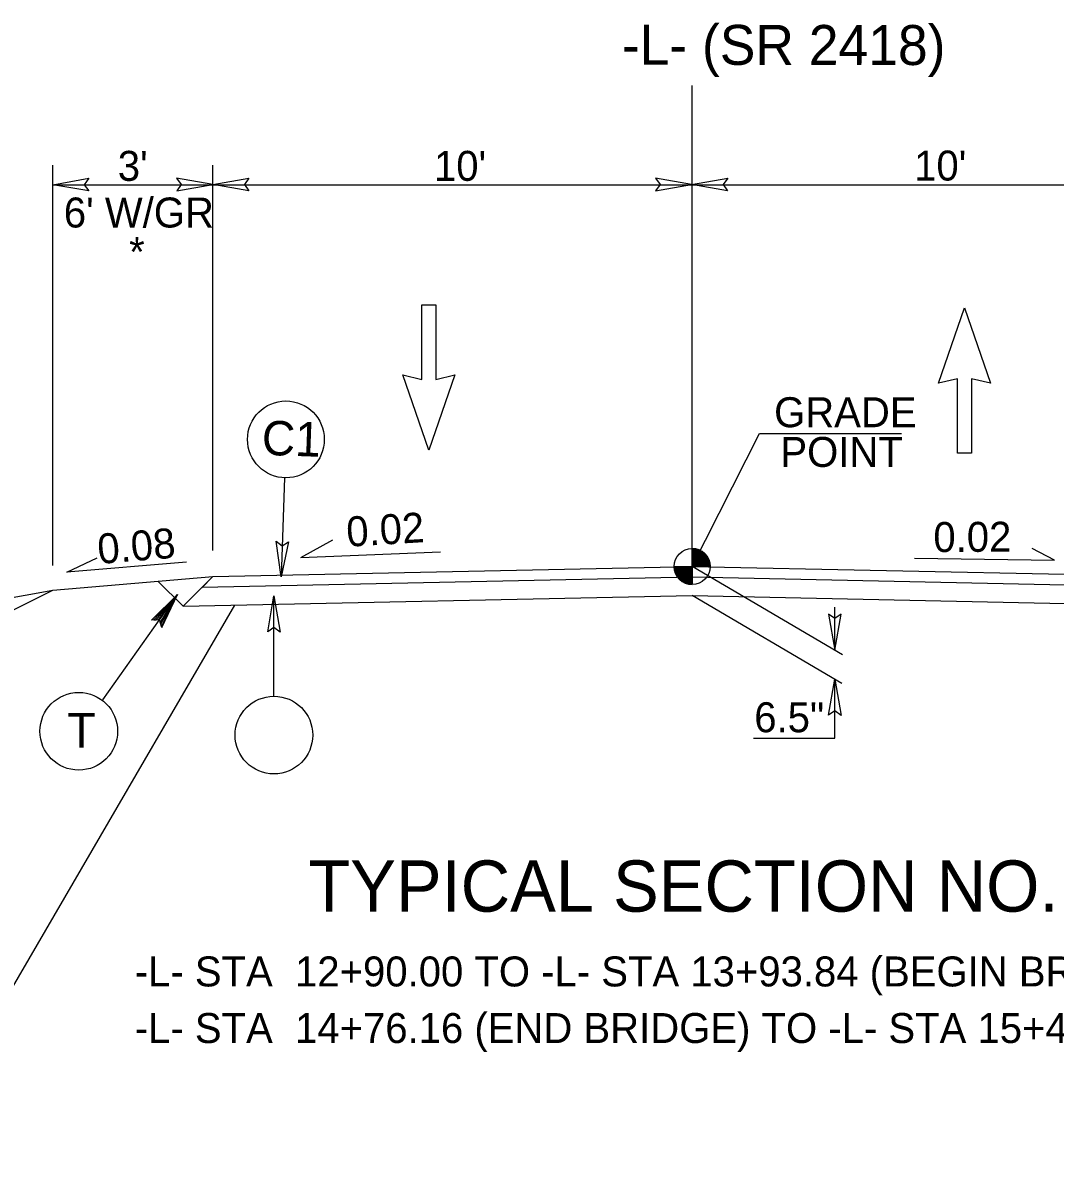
# Model space of a CAD drawing. Extents: x 1542177 to 1542464, y 45134 to 45344.
# Drawn here: x 1542264.12 to 1542284.79, y 45256.85 to 45279.65 of the extents above; entities that cross this region are included whole.
import ezdxf

# ---------------------------------------------------------------- set-up
doc = ezdxf.new("R2010")
doc.units = 0
for name, color, linetype in [('Default', 7, 'Continuous'), ('Old_Level_2', 7, 'Continuous'), ('Typical Detail Wedge3 CELL', 7, 'Continuous'), ('Typical ID Circle CELL', 7, 'Continuous'), ('Typical Terminator CELL', 7, 'Continuous'), ('Typical Text ID Circle CELL', 7, 'Continuous')]:
    doc.layers.add(name, color=color, linetype=linetype)

# ---------------------------------------------------------------- blocks, each defined once
blk = doc.blocks.new('GP')
at = {"layer": 'Default'}
blk.add_line((-0.001, -0.343), (0, 0), dxfattribs=at)
for points in [[(0.343, 0), (0.343, 0), (0, 0), (0, 0.343), (0, 0.343)], [(0.003, 0.343), (0.003, 0.343), (0.003, 0)], [(0.01, 0.343), (0.01, 0)], [(0.017, 0.342), (0.017, 0)], [(0.024, 0.342), (0.024, 0)], [(0.03, 0.341), (0.03, 0)], [(0.037, 0.341), (0.037, 0)], [(0.044, 0.34), (0.044, 0)], [(0.051, 0.339), (0.051, 0)], [(0.058, 0.338), (0.058, 0)], [(0.065, 0.337), (0.065, 0)], [(0.072, 0.335), (0.072, 0)], [(0.079, 0.334), (0.079, 0)], [(0.085, 0.332), (0.085, 0)], [(0.092, 0.33), (0.092, 0)], [(0.099, 0.328), (0.099, 0)], [(0.106, 0.326), (0.106, 0)], [(0.113, 0.324), (0.113, 0)], [(0.12, 0.321), (0.12, 0)], [(0.126, 0.319), (0.126, 0)], [(0.133, 0.316), (0.133, 0)], [(0.14, 0.312), (0.14, 0)], [(0.147, 0.309), (0.147, 0)], [(0.154, 0.306), (0.154, 0)], [(0.161, 0.302), (0.161, 0)], [(0.168, 0.299), (0.168, 0)], [(0.175, 0.295), (0.175, 0)], [(0.181, 0.291), (0.181, 0)], [(0.188, 0.286), (0.188, 0)], [(0.195, 0.282), (0.195, 0)], [(0.202, 0.277), (0.202, 0)], [(0.209, 0.272), (0.209, 0)], [(0.216, 0.267), (0.216, 0)], [(0.223, 0.261), (0.223, 0)], [(0.229, 0.255), (0.229, 0)], [(0.236, 0.248), (0.236, 0)], [(0.243, 0.241), (0.243, 0)], [(0.25, 0.235), (0.25, 0)], [(0.257, 0.227), (0.257, 0)], [(0.264, 0.219), (0.264, 0)], [(-0.343, 0), (0, 0), (-0.001, -0.343), (0, -0.343)], [(-0.343, 0), (-0.343, 0)], [(-0.341, 0), (-0.341, -0.037)], [(-0.335, 0), (-0.335, -0.078)], [(-0.328, 0), (-0.328, -0.102)], [(-0.321, 0), (-0.321, -0.123)], [(-0.314, 0), (-0.314, -0.139)], [(-0.307, 0), (-0.307, -0.153)], [(-0.3, 0), (-0.3, -0.166)], [(-0.293, 0), (-0.293, -0.178)], [(-0.286, 0), (-0.286, -0.189)], [(-0.28, 0), (-0.28, -0.199)], [(-0.273, 0), (-0.273, -0.208)], [(-0.266, 0), (-0.266, -0.216)], [(-0.259, 0), (-0.259, -0.225)], [(-0.252, 0), (-0.252, -0.232)], [(-0.245, 0), (-0.245, -0.24)], [(-0.238, 0), (-0.238, -0.247)], [(-0.232, 0), (-0.232, -0.253)], [(-0.225, 0), (-0.225, -0.259)], [(-0.218, 0), (-0.218, -0.265)], [(-0.211, 0), (-0.211, -0.271)], [(-0.204, 0), (-0.204, -0.276)], [(-0.197, 0), (-0.197, -0.281)], [(-0.191, 0), (-0.191, -0.285)], [(-0.184, 0), (-0.184, -0.29)], [(-0.177, 0), (-0.177, -0.294)], [(-0.17, 0), (-0.17, -0.298)], [(-0.163, 0), (-0.163, -0.302)], [(-0.156, 0), (-0.156, -0.306)], [(-0.149, 0), (-0.149, -0.309)], [(-0.142, 0), (-0.142, -0.312)], [(-0.135, 0), (-0.135, -0.315)], [(-0.129, 0), (-0.129, -0.318)], [(-0.122, 0), (-0.122, -0.321)], [(-0.115, 0), (-0.115, -0.323)], [(-0.108, 0), (-0.108, -0.325)], [(-0.101, 0), (-0.101, -0.328)], [(-0.095, 0), (-0.095, -0.329)], [(-0.088, 0), (-0.088, -0.331)], [(-0.081, 0), (-0.081, -0.333)], [(-0.074, 0), (-0.074, -0.335)], [(-0.067, 0), (-0.067, -0.336)], [(-0.06, 0), (-0.06, -0.338)], [(-0.053, 0), (-0.053, -0.338)], [(-0.046, 0), (-0.046, -0.34)], [(-0.04, 0), (-0.04, -0.341)], [(-0.033, 0), (-0.033, -0.341)], [(-0.026, 0), (-0.026, -0.342)], [(-0.019, 0), (-0.019, -0.342)], [(-0.012, 0), (-0.012, -0.343)], [(-0.005, 0), (-0.005, -0.343), (-0.005, -0.343)], [(0.271, 0.21), (0.271, 0)], [(0.277, 0.201), (0.277, 0)], [(0.284, 0.191), (0.284, 0)], [(0.291, 0.18), (0.291, 0)], [(0.298, 0.169), (0.298, 0)], [(0.305, 0.157), (0.305, 0)], [(0.312, 0.142), (0.312, 0)], [(0.319, 0.126), (0.319, 0)], [(0.326, 0.107), (0.326, 0)], [(0.332, 0.084), (0.332, 0)], [(0.339, 0.049), (0.339, 0)]]:
    blk.add_lwpolyline(points, dxfattribs=at)
blk.add_circle((0, 0), 0.343, dxfattribs=at)
for start, end in [(359.9905, 89.9905), (179.9905, 269.9905)]:
    blk.add_arc((0, 0), 0.343, start, end, dxfattribs=at)
blk = doc.blocks.new('ARROW3')
at = {"layer": 'Default'}
blk.add_lwpolyline([(-0.0267, -0.5547), (-0.0267, -0.2704), (-0.0991, -0.2874), (0, 0), (0.0991, -0.2874), (0.0267, -0.2704), (0.0267, -0.5547), (-0.0267, -0.5547)], dxfattribs=at)
blk = doc.blocks.new('CIR2')
at = {"layer": 'Default'}
blk.add_line((0, -1.914), (0, 0), dxfattribs=at)
blk.add_lwpolyline([(-0.118, -0.686), (0, 0), (0.122, -0.69), (0, -0.602)], close=True, dxfattribs=at)
blk.add_circle((0, -2.655), 0.741, dxfattribs=at)

msp = doc.modelspace()

# ---------------------------------------------------------------- linework, layer by layer
at = {"layer": 'Default'}
for p, q in [((1542277.52, 45268.762), (1542277.52, 45278.397)), ((1542264.715, 45268.783), (1542264.715, 45276.797)), ((1542267.921, 45269.082), (1542267.921, 45276.797)), ((1542264.715, 45276.408), (1542267.921, 45276.408)), ((1542267.921, 45276.408), (1542277.52, 45276.408)), ((1542277.52, 45276.408), (1542287.12, 45276.408)), ((1542277.521, 45268.762), (1542278.868, 45271.426)), ((1542278.868, 45271.426), (1542281.714, 45271.426)), ((1542269.683, 45268.944), (1542270.323, 45269.297)), ((1542269.683, 45268.944), (1542272.481, 45269.055)), ((1542284.775, 45268.888), (1542284.326, 45269.122)), ((1542264.996, 45268.651), (1542265.606, 45268.939)), ((1542267.396, 45268.851), (1542264.996, 45268.651)), ((1542281.975, 45268.932), (1542284.775, 45268.888)), ((1542267.921, 45268.562), (1542277.52, 45268.762)), ((1542267.921, 45268.562), (1542277.521, 45268.762)), ((1542277.52, 45268.762), (1542287.12, 45268.562)), ((1542264.715, 45268.291), (1542267.921, 45268.562)), ((1542267.325, 45267.967), (1542266.823, 45268.469)), ((1542267.921, 45268.562), (1542267.325, 45267.967)), ((1542267.698, 45268.339), (1542267.921, 45268.562)), ((1542267.698, 45268.339), (1542267.921, 45268.562)), ((1542267.708, 45268.349), (1542277.525, 45268.554)), ((1542277.516, 45268.554), (1542287.333, 45268.35)), ((1542256.708, 45264.287), (1542264.715, 45268.291)), ((1542256.891, 45266.86), (1542264.715, 45268.291)), ((1542267.325, 45267.967), (1542277.52, 45268.179)), ((1542277.52, 45268.179), (1542287.716, 45267.967))]:
    msp.add_line(p, q, dxfattribs=at)
for points in [[(1542265.435, 45276.284), (1542264.715, 45276.408), (1542265.439, 45276.536), (1542265.347, 45276.408)], [(1542267.201, 45276.286), (1542267.921, 45276.41), (1542267.197, 45276.538), (1542267.289, 45276.41)], [(1542268.641, 45276.286), (1542267.921, 45276.41), (1542268.645, 45276.538), (1542268.553, 45276.41)], [(1542276.789, 45276.285), (1542277.509, 45276.409), (1542276.785, 45276.537), (1542276.877, 45276.409)], [(1542278.229, 45276.285), (1542277.509, 45276.409), (1542278.233, 45276.537), (1542278.141, 45276.409)], [(1542280.251, 45267.807), (1542280.375, 45267.087), (1542280.503, 45267.811), (1542280.375, 45267.719)], [(1542280.251, 45265.784), (1542280.375, 45266.504), (1542280.503, 45265.78), (1542280.375, 45265.872)]]:
    msp.add_lwpolyline(points, close=True, dxfattribs=at)
at = {"layer": 'Old_Level_2'}
msp.add_lwpolyline([(1542268.353, 45267.988), (1542261.876, 45256.854), (1542260.626, 45256.854)], dxfattribs=at)
at = {"layer": 'Typical Detail Wedge3 CELL'}
msp.add_lwpolyline([(1542266.901, 45267.543), (1542266.852, 45267.693), (1542266.692, 45267.691), (1542267.213, 45268.203), (1542266.738, 45267.692), (1542266.784, 45267.693), (1542267.213, 45268.203), (1542266.828, 45267.693), (1542266.852, 45267.693), (1542267.213, 45268.203), (1542266.864, 45267.651), (1542266.879, 45267.608), (1542267.213, 45268.203), (1542266.893, 45267.565), (1542266.901, 45267.543), (1542267.213, 45268.203)], dxfattribs=at)
at = {"layer": 'Typical ID Circle CELL'}
for p, q in [((1542269.359, 45270.54), (1542269.289, 45268.553)), ((1542280.53, 45266.995), (1542277.52, 45268.762)), ((1542280.518, 45266.42), (1542277.52, 45268.179)), ((1542280.375, 45267.087), (1542280.375, 45267.951)), ((1542265.719, 45266.091), (1542266.852, 45267.693)), ((1542280.375, 45265.326), (1542280.375, 45266.504)), ((1542278.751, 45265.326), (1542280.375, 45265.326))]:
    msp.add_line(p, q, dxfattribs=at)
for centre, radius in [((1542269.385, 45271.308), 0.769), ((1542265.237, 45265.464), 0.778)]:
    msp.add_circle(centre, radius, dxfattribs=at)
at = {"layer": 'Typical Terminator CELL'}
msp.add_lwpolyline([(1542269.437, 45269.26), (1542269.289, 45268.553), (1542269.188, 45269.273), (1542269.311, 45269.177)], close=True, dxfattribs=at)

# ---------------------------------------------------------------- block references
at = {"layer": 'Default', "xscale": 5.249333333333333, "yscale": 5.249333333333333, "rotation": 180}
msp.add_blockref('ARROW3', (1542272.248, 45271.091), dxfattribs=at)
at = {"layer": 'Default'}
for name, p, xscale, yscale in [('ARROW3', (1542282.976, 45273.942), 5.249333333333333, 5.249333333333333), ('GP', (1542277.521, 45268.762), 1.0498642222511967, 1.0498642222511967), ('CIR2', (1542269.144, 45268.174), 1.0498642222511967, 1.0498642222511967)]:
    msp.add_blockref(name, p, dxfattribs=dict(at, xscale=xscale, yscale=yscale))

# ---------------------------------------------------------------- texts
for s, height, rotation, p in [('-L- (SR 2418)', 0.8, 359.9469, (1542276.112, 45278.81)), ('0.02', 0.6, 3.4691, (1542270.613, 45269.157)), ('0.08', 0.6, 4.7617, (1542265.636, 45268.812)), ('0.02', 0.6, 0.2853, (1542282.352, 45269.052))]:
    msp.add_text(s, height=height, rotation=rotation, dxfattribs=at).set_placement(p)
for s, height, p in [("3'", 0.6, (1542266.018, 45276.485)), ("10'", 0.6, (1542272.35, 45276.485)), ("10'", 0.6, (1542281.966, 45276.491)), ("6' W/GR", 0.6, (1542264.937, 45275.551)), ('*', 0.6, (1542266.245, 45274.764)), ('GRADE', 0.6, (1542279.161, 45271.552)), ('POINT', 0.6, (1542279.287, 45270.757)), ('TYPICAL SECTION NO. 2', 1.02627, (1542269.834, 45261.851)), ('-L- STA  12+90.00 TO -L- STA 13+93.84 (BEGIN BRIDGE)', 0.6, (1542266.358, 45260.354)), ('-L- STA  14+76.16 (END BRIDGE) TO -L- STA 15+40.00', 0.6, (1542266.358, 45259.221))]:
    msp.add_text(s, height=height, dxfattribs=at).set_placement(p)
at = {"layer": 'Typical ID Circle CELL'}
msp.add_text('6.5"', height=0.6, dxfattribs=at).set_placement((1542278.764, 45265.444))
at = {"layer": 'Typical Text ID Circle CELL'}
msp.add_text('C1', height=0.6886, rotation=358, dxfattribs=at).set_placement((1542268.894, 45271))
msp.add_text('T', height=0.696, dxfattribs=at).set_placement((1542265.009, 45265.136))

doc.saveas('drawing.dxf')
